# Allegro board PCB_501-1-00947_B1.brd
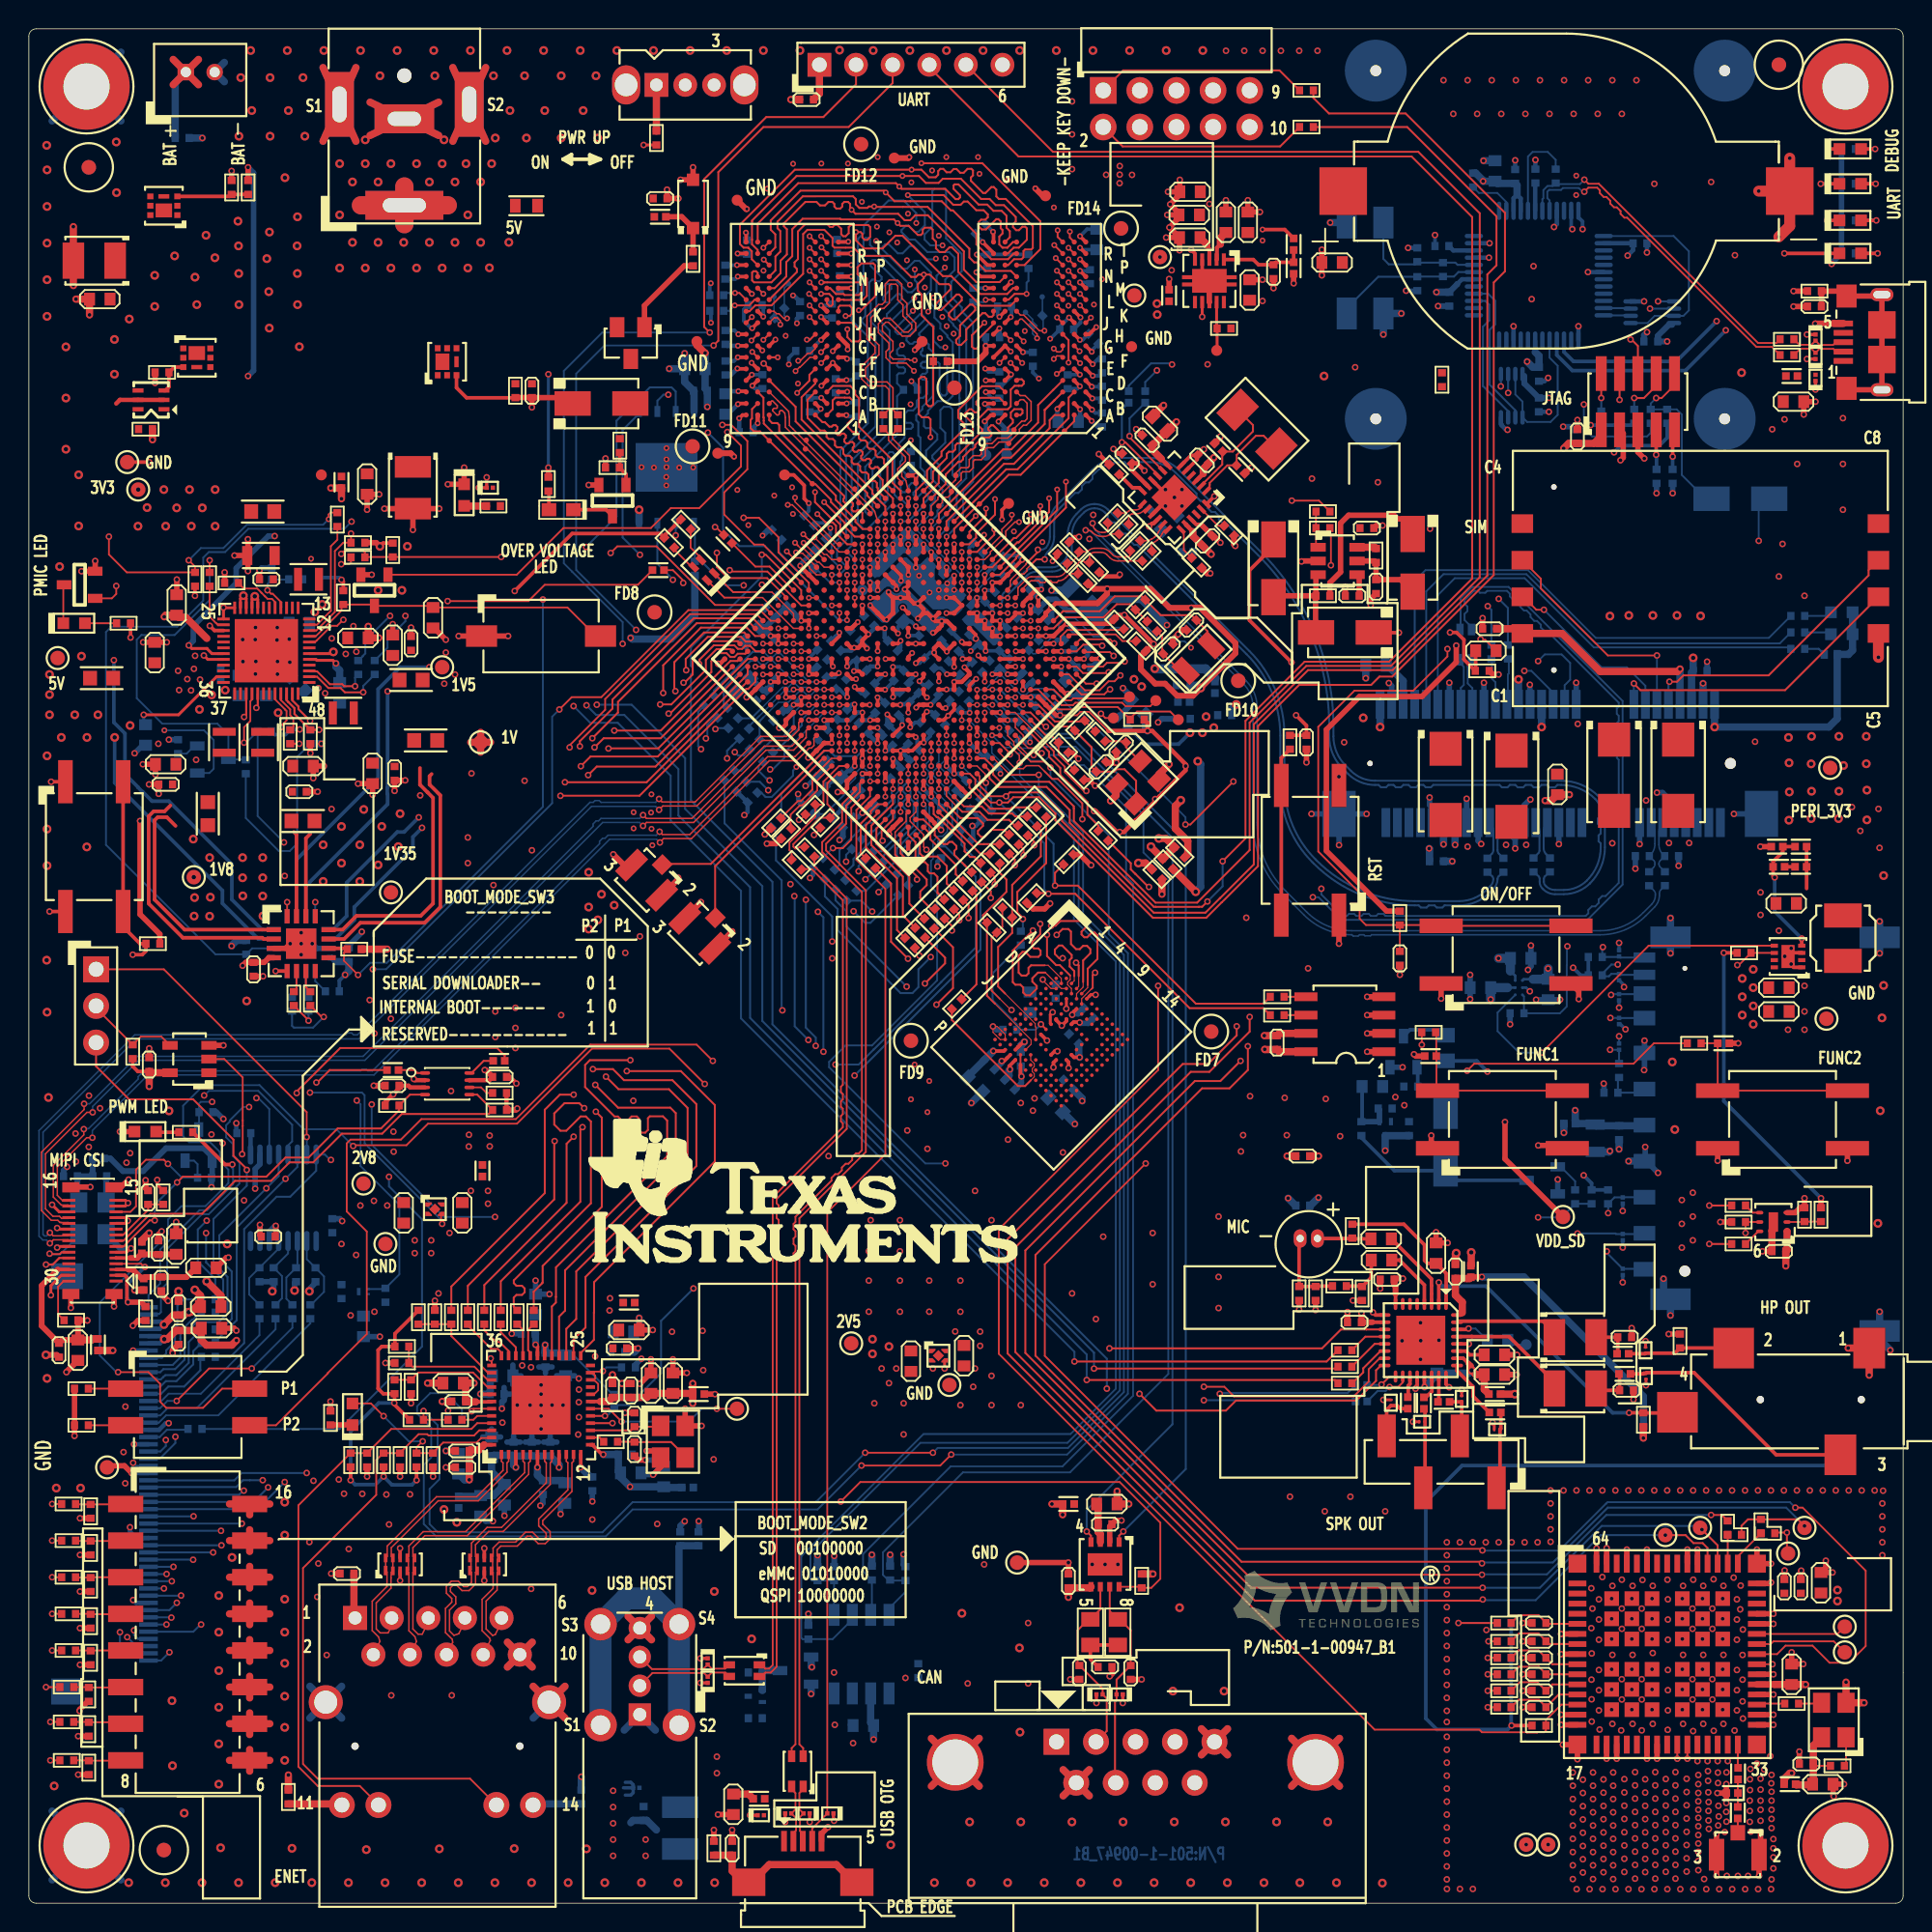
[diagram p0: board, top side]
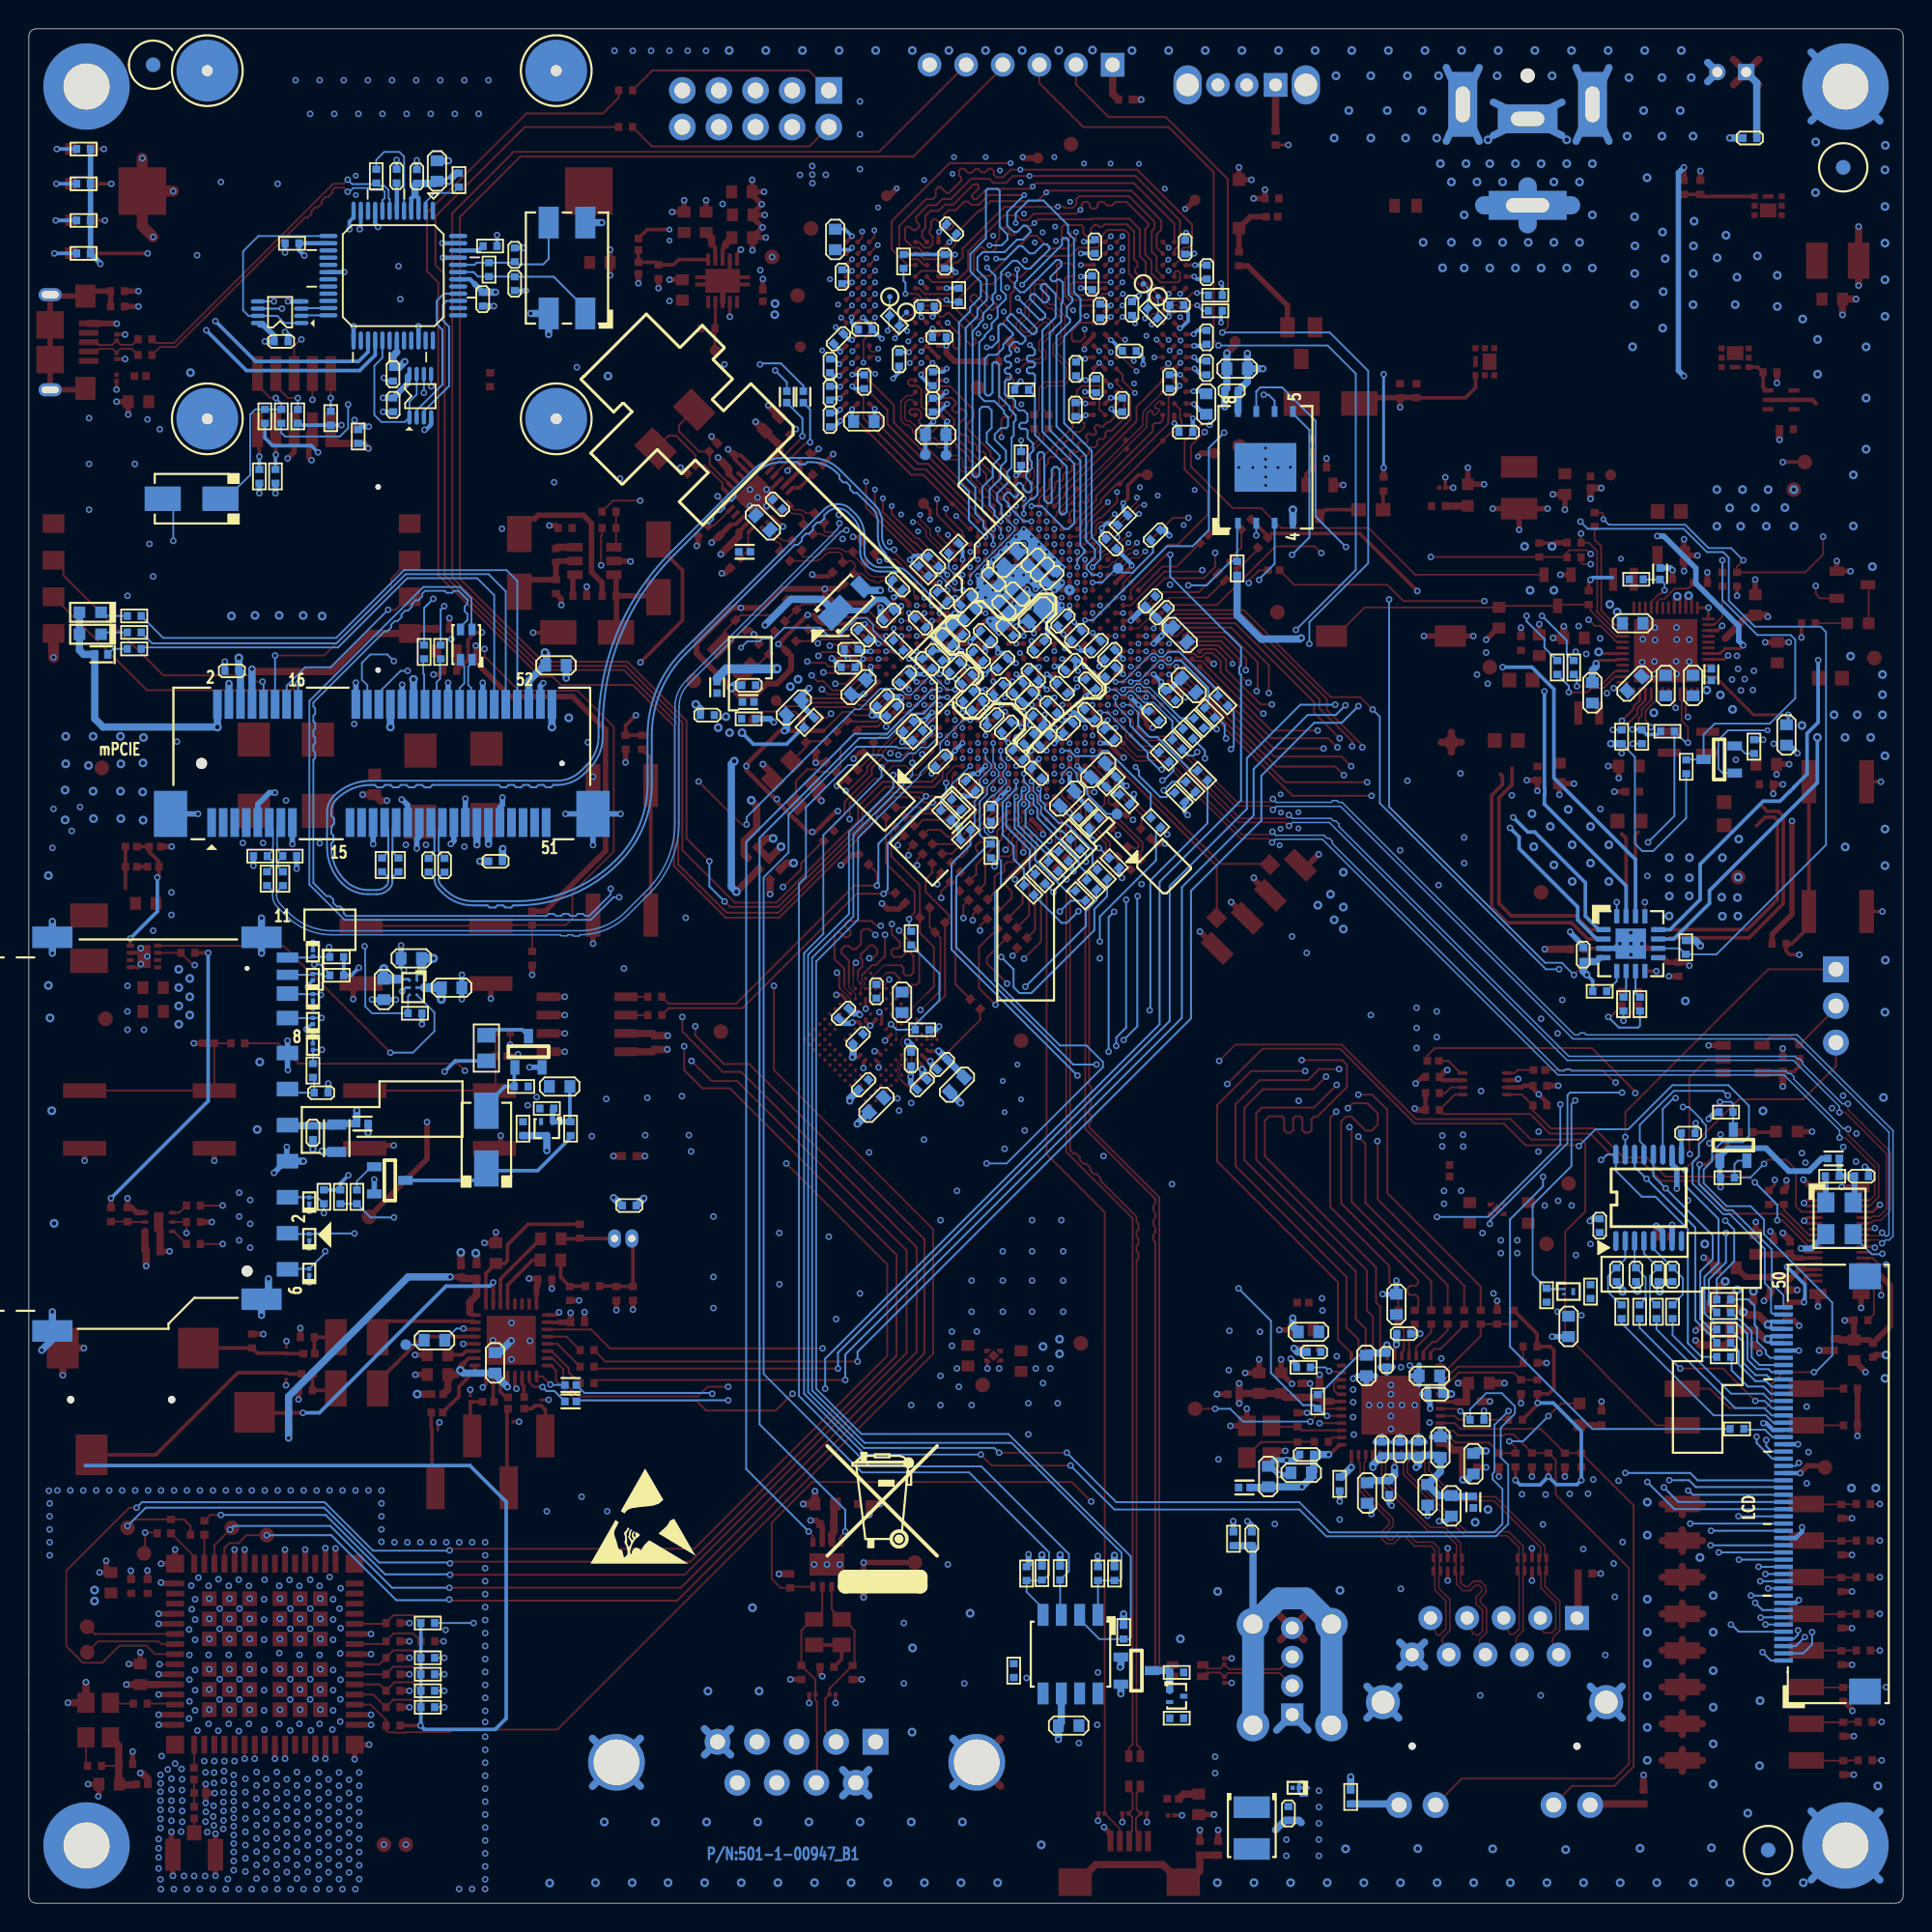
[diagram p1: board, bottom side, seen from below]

Outline 130 x 130 mm; copper layers: TOP, L2_GND_1, L3_INT_1, L4_PWR_1, L5_PWR_2, L6_INT_2, L7_GND_2, BOTTOM. Coordinates in mm from the lower left corner of the outline.
Outline path: 0,129.49 0,0.51 arc(0.15,0.15) 0.51,0 129.49,0 arc(129.85,0.15) 130,0.51 130,129.49 arc(129.85,129.85) 129.49,130 0.51,130 arc(0.15,129.85) 0,129.49

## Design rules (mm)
constraint set DEFAULT: min track width 0.127
net group D_USB_1: nets D_USB_DN D_USB_DP
net group DIFFPAIR63: nets MIPI_CSI_D0_N MIPI_CSI_D0_P
net group DIFFPAIR64: nets MIPI_CSI_D1_N MIPI_CSI_D1_P
net group DIFFPAIR65: nets MIPI_CSI_CLK_N MIPI_CSI_CLK_P
net group DIFFPAIR72: nets DDR_SDCLK0_N DDR_SDCLK0_P
net group DIFFPAIR75: nets CLKGEN_Q0_N CLKGEN_Q0_P
net group ETH-50OHMS: nets ENET_MDC ENET_MDIO
net group GPIO_SD3_DATA0: nets GPIO_SD3_DATA0 SD3_DATA0
net group GPIO_SD3_DATA1: nets GPIO_SD3_DATA1 SD3_DATA1
net group GPIO_SD3_DATA2: nets GPIO_SD3_DATA2 SD3_DATA2
net group GPIO_SD3_DATA3: nets GPIO_SD3_DATA3 SD3_DATA3
net group GPIO_SD3_DATA4: nets GPIO_SD3_DATA4 SD3_DATA4
net group GPIO_SD3_DATA5: nets GPIO_SD3_DATA5 SD3_DATA5
net group GPIO_SD3_DATA6: nets GPIO_SD3_DATA6 SD3_DATA6
net group GPIO_SD3_DATA7: nets GPIO_SD3_DATA7 SD3_DATA7
net group I2C_PCIE: nets PCIE_SMB_CLK PCIE_SMB_DATA
net group PCIE: nets PCIE_TX_N PCIE_TX_P
net group PCIE_CN: nets PCIE_CTXM PCIE_CTXP
net group PCIE_CREFCLK: nets PCIE_REFCLKOUT_N PCIE_REFCLKOUT_P
net group PCIE_REF-CLK_1: nets CLKGEN_Q1_N CLKGEN_Q1_P
net group PCIE_REFCLK: nets PCIE_REFCLK_N PCIE_REFCLK_P
net group PCIE_REFCLK-OUT: nets PCIE_REFCLKOUT_N0 PCIE_REFCLKOUT_P0
net group PCIE_RX_N: nets PCIE_RX_N PCIE_RXN_R
net group PCIE_RX_P: nets PCIE_RX_P PCIE_RXP_R
net group PCIE_USB_D: nets PCIE_USB_DM PCIE_USB_DP
net group RGMII1_RX_CTL: nets RGMII1_RX_CTL RX_CTRL
net group RGMII1_RXC: nets RGMII1_RXC RX_CLK
net group RGMII1_RXD0: nets RGMII1_RXD0 RX_D0
net group RGMII1_RXD1: nets RGMII1_RXD1 RX_D1
net group RGMII1_RXD2: nets RGMII1_RXD2 RX_D2
net group RGMII1_RXD3: nets RGMII1_RXD3 RX_D3
net group RGMII1_TX_CTL: nets RGMII1_TX_CTL RGMII_TCTRL
net group RGMII1_TXC: nets RGMII1_TXC RGMII_TXC
net group RGMII1_TXD0: nets RGMII1_TXD0 RGMII_TD0
net group RGMII1_TXD1: nets RGMII1_TXD1 RGMII_TD1
net group RGMII1_TXD2: nets RGMII1_TXD2 RGMII_TD2
net group RGMII1_TXD3: nets RGMII1_TXD3 RGMII_TD3
net group SD1_CMD: nets SD1_CMD SOC_SD1_CMD
net group SD2_CLK: nets SD2_CLK SOC_SD2_CLK
net group SPKOUTR: nets SPKRN SPKRP
net group USB_D2: nets USB_DN USB_DP
net group USB_HOST: nets USB_HOST_N USB_HOST_P
net group USB_HOST_D: nets USB_PCIE_DN USB_PCIE_DP
net group USB_OTG: nets USB_OTG_N USB_OTG_P
net group USB_OTG1_D: nets USB_OTG1_DN USB_OTG1_DP
net group USB_OTG2_DN: nets SOC_OTG2_DN USB_OTG2_DN
net group USB_OTG2_DP: nets SOC_OTG2_DP USB_OTG2_DP
net group GPIO_SD3_CMD: nets GPIO_SD3_CMD
net group LCD1_CLK: nets LCD1_CLK
net group PCIE_UIM: nets PCIE_UIM_CLK PCIE_UIM_DATA PCIE_UIM_PWR PCIE_UIM_RST PCIE_UIM_VPP
net group SD1_CLK: nets SOC_SD1_CLK
net group SD1_DATA0: nets SOC_SD1_DATA0
net group SD1_DATA1: nets SOC_SD1_DATA1
net group SD1_DATA2: nets SOC_SD1_DATA2
net group SD1_DATA3: nets SOC_SD1_DATA3
net group SD2_CMD: nets SOC_SD2_CMD
net group SD2_DATA0: nets SOC_SD2_DATA0
net group SD2_DATA1: nets SOC_SD2_DATA1
net group SD2_DATA2: nets SOC_SD2_DATA2
net group SD2_DATA3: nets SOC_SD2_DATA3
net group SD3_CLK_R: nets GPIO_SD3_CLK SD3_CLK SD3_CLK_R
net group SD3_RESET_B: nets GPIO_SD3_RESET_B
net group SD3_STROBE: nets GPIO_SD3_STROBE SD3_STROBE SD3_STROBE_R
net group SPKOUTL: nets SPKLP SPKOUTLN SPKOUTLP
net group WL_SD: nets WL_SDIO_CLK WL_SDIO_CMD WL_SDIO_D0 WL_SDIO_D1 WL_SDIO_D2 WL_SDIO_D3
nets with their own width: min track width 0.127; nets GND

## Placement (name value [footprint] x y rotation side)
BH1  BU2032SM-JJ-GTR  [CON_BATTERY_2F_30P97_SM]  106.65 118.75 0 top
C1  100uF  [TCAP_CASEB]  26.64 98.17 270 top
C2  22uF  [C0603]  23.46 98.42 270 top
C3  1uF  [0402]  21.68 98.55 270 top
C40  22uF  [C0603]  23.84 78.36 270 top
C41  22uF  [C0603]  19.02 78.87 0 top
C42  22uF  [C0603]  9.49 78.99 180 top
C44  22uF  [C0603]  25.24 87.25 90 top
C45  22uF  [C0603]  10.25 90.04 90 top
C46  47uF  [0805_B_A1]  16.1 93.47 180 top
C47  0.1uF  [C0402]  16.48 91.82 180 top
C48  22uF  [C0603]  22.83 87.76 0 top
C49  22uF  [C0603]  8.73 86.74 90 top
C50  4.7uF  [C0603]  18.64 84.58 135 bottom
C51  4.7uF  [C0603]  14.57 84.45 90 bottom
C52  4.7uF  [C0603]  18.76 88.77 180 bottom
C53  4.7uF  [C0603]  16.48 84.45 90 bottom
C63  0.22uF  [C0402]  52.21 90.32 135 bottom
C64  0.22uF  [C0402]  51.41 89.5 135 bottom
C65  22uF  [C0603]  49.55 84.48 225 bottom
C66  0.22uF  [C0402]  65.57 88.33 225 bottom
C67  2.2uF  [C0402]  60.33 85.15 45 bottom
C68  0.22uF  [C0402]  63.27 75.5 270 bottom
C69  0.22uF  [C0402]  64.68 77.5 225 bottom
C70  0.22uF  [C0402]  55.04 81.06 225 bottom
C71  0.22uF  [C0402]  51.96 82.35 225 bottom
C72  0.22uF  [C0402]  50.81 83.76 225 bottom
C73  22uF  [C0603]  50.17 87.96 225 bottom
C74  0.22uF  [C0402]  66.66 90.61 45 bottom
C75  0.22uF  [C0402]  65.01 90.35 135 bottom
C76  2.2uF  [C0402]  68.16 88.8 45 bottom
C77  2.2uF  [C0402]  57.75 85.85 315 bottom
C78  0.22uF  [C0402]  66.3 87.62 225 bottom
C79  0.22uF  [C0402]  68.99 81.61 315 bottom
C80  0.22uF  [C0402]  62.36 89.88 45 bottom
C81  0.22uF  [C0402]  62.08 88.26 225 bottom
C82  0.22uF  [C0402]  66.77 79.19 315 bottom
C83  0.22uF  [C0402]  61.41 90.81 45 bottom
C84  0.22uF  [C0402]  54.98 85.38 315 bottom
C85  22uF  [C0603]  60.15 89.39 315 bottom
C86  0.22uF  [C0402]  70.82 83.37 315 bottom
C87  2.2uF  [C0402]  70.14 82.68 315 bottom
C88  0.22uF  [C0402]  59.05 82.9 225 bottom
C89  2.2uF  [C0402]  64.14 86.48 225 bottom
C90  0.22uF  [C0402]  80.07 84.47 0 bottom
C91  2.2uF  [C0402]  67.69 85.98 45 bottom
C92  0.22uF  [C0402]  55.03 86.6 135 bottom
C93  0.22uF  [C0402]  66.97 86.52 45 bottom
C94  0.22uF  [C0402]  70.37 89.32 315 bottom
C95  2.2uF  [C0402]  69.74 91.44 45 bottom
C96  4.7uF  [C0603]  76.94 82.93 315 bottom
C97  2.2uF  [C0402]  72.14 87.97 45 bottom
C98  0.22uF  [C0402]  64.91 84.88 315 bottom
C99  0.22uF  [C0402]  65.78 85.72 315 bottom
C100  2.2uF  [C0402]  63.65 87.91 225 bottom
C101  0.22uF  [C0402]  56.41 82.45 45 bottom
C102  18pF  [C0402]  80.64 88.65 225 top
C103  18pF  [C0402]  79.01 87 45 top
C104  0.22uF  [C0402]  60.12 78.37 225 bottom
C105  18pF  [C0402]  74.38 78.82 45 top
C106  18pF  [C0402]  75.76 80.17 225 top
C107  0.22uF  [C0402]  69.27 84.99 315 bottom
C108  0.22uF  [C0402]  61.42 79.63 225 bottom
C109  2.2uF  [C0402]  55.98 87.22 135 bottom
C110  0.22uF  [C0402]  63.2 82.07 315 bottom
C111  2.2uF  [C0402]  62.18 81.56 315 bottom
C112  0.47uF  [C0402]  58.28 88.94 135 bottom
C113  0.47uF  [C0402]  56.35 84.56 225 bottom
C114  0.47uF  [C0402]  57.32 87.92 135 bottom
C115  2.2uF  [C0402]  58.33 84.25 45 bottom
C116  2.2uF  [C0402]  59.92 87.21 315 bottom
C117  0.22uF  [C0402]  57.9 81.51 135 bottom
C118  0.22uF  [C0402]  64.21 83.08 315 bottom
C119  0.22uF  [C0402]  60 82.05 45 bottom
C120  2.2uF  [C0402]  60.64 80.75 315 bottom
C121  10uF  [C0603]  57.99 76.62 315 bottom
C122  0.22uF  [C0402]  59.55 80.63 135 bottom
C123  10uF  [C0603]  55.83 78.58 135 bottom
C124  0.22uF  [C0402]  62.74 84.17 135 bottom
C125  0.22uF  [C0402]  60.75 83.65 135 bottom
C126  2.2uF  [C0402]  61.37 84.28 135 bottom
C127  0.22uF  [C0402]  64.85 83.7 315 bottom
C128  2.2uF  [C0402]  62.45 86 135 bottom
C129  0.22uF  [C0402]  82.94 82.4 0 bottom
C130  0.22uF  [C0402]  72.96 86.97 0 bottom
C131  2.2uF  [C0402]  73.17 85.72 0 bottom
C140  0.22uF  [C0402]  54.93 94.28 225 bottom
C141  0.1uF  [C0402]  67.26 93.05 45 bottom
C142  0.22uF  [C0402]  50.38 110.84 180 bottom
C143  0.22uF  [C0402]  50.88 105.53 270 bottom
C144  0.22uF  [C0402]  57.41 103.59 90 bottom
C145  0.22uF  [C0402]  66 116.12 45 bottom
C146  0.22uF  [C0402]  53.49 110.6 270 bottom
C147  0.22uF  [C0402]  56.06 114.91 90 bottom
C148  22uF  [C0603]  61.92 93.17 315 bottom
C149  0.22uF  [C0402]  56.25 112.39 270 bottom
C150  0.22uF  [C0402]  55.7 110.43 270 bottom
C151  0.22uF  [C0402]  55.96 105.24 90 bottom
C152  0.22uF  [C0402]  48.32 106.48 90 bottom
C153  0.22uF  [C0402]  67.31 103.9 270 bottom
C154  0.22uF  [C0402]  63.09 91.82 225 bottom
C155  0.22uF  [C0402]  54.16 103.91 270 bottom
C156  22uF  [C0603]  67.1 101.84 180 bottom
C157  0.22uF  [C0402]  48.3 113.13 90 bottom
C158  0.22uF  [C0402]  67.31 105.72 270 bottom
C159  0.22uF  [C0402]  74.43 104.73 90 bottom
C160  0.22uF  [C0402]  53.67 107.66 180 bottom
C161  0.22uF  [C0402]  73.6 112.81 270 bottom
C162  0.22uF  [C0402]  74.43 106.62 270 bottom
C163  0.22uF  [C0402]  72.05 105.52 90 bottom
C164  22uF  [C0603]  74.07 115.39 90 bottom
C165  0.22uF  [C0402]  71.98 109.15 180 bottom
C166  0.22uF  [C0402]  73.85 108.5 315 bottom
C167  0.22uF  [C0402]  67.68 110.74 0 bottom
C168  0.22uF  [C0402]  69.64 107.08 270 bottom
C169  0.22uF  [C0402]  49.8 114.86 90 bottom
C170  0.22uF  [C0402]  66.85 108.61 180 bottom
C171  0.22uF  [C0402]  60.34 93.14 315 bottom
C172  22uF  [C0603]  48.34 103.98 270 bottom
C173  0.22uF  [C0402]  59.05 91.92 315 bottom
C174  0.22uF  [C0402]  66.48 113.87 90 bottom
C175  0.22uF  [C0402]  48.32 108.6 270 bottom
C176  0.22uF  [C0402]  57.37 106.41 270 bottom
C177  0.22uF  [C0402]  49.75 102.03 180 bottom
C178  0.22uF  [C0402]  74.44 102.87 90 bottom
C179  0.22uF  [C0402]  59.71 92.51 315 bottom
C180  22uF  [C0603]  72.09 102.77 180 bottom
C181  0.1uF  [C0402]  72.48 59.94 315 bottom
C182  0.1uF  [C0402]  72.1 56.77 315 bottom
C183  4.7uF  [C0603]  71.21 55.37 315 bottom
C184  0.1uF  [C0402]  66.64 58.17 315 bottom
C185  0.1uF  [C0402]  68.04 56.77 315 bottom
C186  0.1uF  [C0402]  68.8 58.55 270 bottom
C187  0.1uF  [C0402]  73.5 61.72 315 bottom
C188  4.7uF  [C0603]  65.63 56.77 315 bottom
C189  4.7uF  [C0603]  46.19 106.43 0 bottom
C190  0.22uF  [C0402]  46.58 104.9 0 bottom
C194  1uF  [C0603]  93.18 56.64 180 bottom
C195  47uF  [0805_B_A1]  108.64 53.05 270 bottom
C196  0.1uF  [C0402]  110.3 53.43 270 bottom
C197  18pF  [C0402]  109.73 56.21 180 bottom
C199  100uF  [TCAP_CASEC]  114.39 78.23 270 top
C200  4.7uF  [C0603]  106.01 77.6 270 top
C201  0.1uF  [C0402]  97.63 72.26 180 bottom
C202  100uF  [TCAP_CASEC]  102.84 77.47 270 top
C203  100uF  [TCAP_CASEC]  98.26 77.6 270 top
C204  100uF  [TCAP_CASEC]  109.95 78.23 270 top
C207  0.1uF  [C0402]  102.27 71.99 90 bottom
C208  0.1uF  [C0402]  101.17 71.99 90 bottom
C216  1uF  [C0603]  122.27 15.88 90 top
C217  0.1uF  [C0402]  122.9 21.97 90 top
C218  10uF  [C0603]  124.3 22.22 90 top
C219  18pF  [C0402]  104.74 13.59 180 top
C220  18pF  [C0402]  104.74 14.73 180 top
C221  18pF  [C0402]  104.74 15.88 180 top
C222  18pF  [C0402]  104.74 17.02 180 top
C223  18pF  [C0402]  104.74 19.43 180 top
C224  18pF  [C0402]  104.74 18.16 180 top
C226  10uF  [C0603]  101.69 120.14 90 bottom
C227  0.1uF  [C0402]  98.52 111.25 270 bottom
C228  0.1uF  [C0402]  104.74 106.05 270 bottom
C239  4.7uF  [C0603]  122.39 104.14 0 top
C240  0.1uF  [C0402]  104.49 119.79 90 bottom
C241  0.22uF  [C0402]  112.5 108.32 180 bottom
C242  0.1uF  [C0402]  123.85 110.74 180 top
C243  18pF  [C0402]  96.3 112.32 90 bottom
C244  18pF  [C0402]  96.3 114.33 270 bottom
C245  0.22uF  [C0402]  104.73 103.92 270 bottom
C249  1uF  [C0603]  37.23 37.29 270 bottom
C250  1uF  [C0603]  43.15 36.07 90 top
C251  0.01uF  [C0402]  40.99 38.48 0 top
C252  0.1uF  [C0402]  48.78 3.81 90 top
C260  1uF  [C0603]  93.82 44.6 180 top
C261  22uF  [C0603]  12.62 41.38 0 top
C262  0.1uF  [C0402]  10.38 41.27 90 top
C263  22uF  [C0603]  12.67 39.88 0 top
C264  0.1uF  [C0402]  10.38 39.23 270 top
C265  0.22uF  [C0402]  21.05 46.99 90 bottom
C266  0.1uF  [C0402]  14.91 53.41 0 bottom
C267  0.1uF  [C0402]  91.94 40.29 180 top
C268  0.1uF  [C0402]  94.21 43.26 180 top
C269  4.7uF  [C0603]  97.66 37.47 90 bottom
C270  4.7uF  [C0603]  101.65 36.66 0 top
C271  0.1uF  [C0402]  98.94 43.81 90 top
C272  4.7uF  [C0603]  97.6 45.09 90 top
C273  4.7uF  [C0603]  101.65 38.03 0 top
C274  100uF  [TCAP_CASEB]  107.26 39.25 0 top
C275  100uF  [TCAP_CASEB]  107.26 35.7 0 top
C276  1uF  [C0603]  101.87 39.04 0 bottom
C279  0.1uF  [C0402]  74.64 26.29 0 top
C280  10uF  [C0603]  44.04 29.59 90 bottom
C281  56pF  [C0402]  72.86 16 270 top
C282  56pF  [C0402]  76.42 16 270 top
C283  0.1uF  [C0402]  30.07 30.23 180 top
C284  1uF  [C0603]  41.75 29.84 0 bottom
C285  1uF  [C0603]  29.81 30.48 90 bottom
C286  10uF  [C0603]  31.34 27.56 270 bottom
C287  0.01uF  [C0402]  36.16 31.5 90 bottom
C288  0.1uF  [C0402]  34.89 31.5 90 bottom
C289  0.1uF  [C0402]  33.62 31.5 90 bottom
C290  1uF  [C0603]  32.1 31.62 90 bottom
C291  1uF  [C0603]  32.99 28.32 270 bottom
C292  10uF  [C0603]  44.67 36.07 90 top
C293  0.01uF  [C0402]  40.48 35.56 90 top
C294  0.1uF  [C0402]  41.75 35.56 90 top
C295  0.1uF  [C0402]  32.48 35.31 0 bottom
C296  0.1uF  [C0402]  35.83 37.67 270 bottom
C297  1uF  [C0603]  32.86 36.58 0 bottom
C298  4.7uF  [C0603]  48.86 6.86 270 top
C299  100uF  [TCAP_CASEB]  45.18 5.21 270 bottom
C300  0.1uF  [C0402]  42.64 6.22 90 bottom
C301  0.1uF  [C0402]  45.18 25.27 90 bottom
C302  0.1uF  [C0402]  35.65 28.83 270 bottom
C303  0.1uF  [C0402]  34.64 39.5 180 bottom
C304  18pF  [C0402]  42 31.5 270 top
C305  18pF  [C0402]  42 33.53 90 top
C306  0.1uF  [C0402]  40.86 38.23 0 bottom
C307  0.1uF  [C0402]  29.81 34.8 180 top
C308  1uF  [C0603]  35.15 41.53 90 bottom
C309  1uF  [C0603]  41.24 39.62 0 bottom
C310  1uF  [C0603]  29.43 36.07 180 top
C311  1uF  [C0603]  37.18 28.45 270 bottom
C318  1uF  [C0603]  93.79 46.08 180 top
C354  4.7uF  [C0603]  10.22 45.71 90 top
C357  0.22uF  [C0402]  64.73 89.39 135 bottom
C361  0.1uF  [C0402]  103.09 119.76 90 bottom
C362  22uF  [C0603]  72.46 84.34 315 bottom
C366  18pF  [C0402]  51.86 94.89 135 bottom
C367  0.1uF  [C0402]  95.09 65.53 270 top
C368  0.1uF  [C0402]  88.61 80.52 270 top
C369  1000pF  [C0402]  110.69 39.25 0 top
C370  1000pF  [C0402]  110.81 35.57 0 top
C382  1uF  [C0603]  101.06 86.87 180 top
C391  0.1uF  [C0402]  121.38 45.21 180 top
C392  0.1uF  [C0402]  8.35 58.17 90 top
C393  0.033uF  [C0402]  91.79 90.68 180 top
C394  0.01uF  [C0402]  34.89 104.9 270 top
C395  0.1uF  [C0402]  43.78 118.24 0 top
C401  2.2uF  [C0402]  93.44 91.31 270 top
C402  27pF  [0402]  84.04 99.44 315 top
C403  27pF  [0402]  82.52 100.97 135 top
C404  10uF  [C0603]  79.09 95.76 45 bottom
C405  0.1uF  [C0402]  78.07 97.03 45 bottom
C406  1uF  [C0603]  78.45 102.62 135 top
C407  0.01uF  [C0402]  76.17 100.2 135 top
C408  0.22uF  [C0402]  86.58 59.69 90 top
C409  0.01uF  [C0402]  81.75 94.49 45 top
C410  0.01uF  [C0402]  81.37 100.08 135 top
C420  18pF  [C0402]  19.88 43.59 90 bottom
C421  18pF  [C0402]  18.53 43.59 90 bottom
C422  18pF  [C0402]  16.98 43.59 90 bottom
C423  18pF  [C0402]  15.99 43.59 90 bottom
C438  100uF  [TCAP_CASEB]  4.54 113.92 180 top
C439  22uF  [C0603]  4.92 111.25 180 top
C444  0.1uF  [C0402]  9.19 42.95 270 top
C445  4.7uF  [C0603]  12.29 44.07 0 top
C446  0.1uF  [C0402]  2.09 38.35 270 top
C447  4.7uF  [C0603]  3.4 38.35 270 top
C448  0.1uF  [C0402]  2.89 50.42 180 bottom
C456  0.1uF  [C0402]  8.27 48.95 90 top
C460  0.1uF  [C0402]  32.65 57.31 0 top
C461  0.1uF  [C0402]  25.2 56.7 180 top
C500  10uF  [C0603]  41.62 39.75 0 top
C501  0.1uF  [C0402]  8.98 45.47 90 top
C503  0.1uF  [C0402]  115.92 85.47 0 bottom
C504  4.7uF  [C0603]  93.44 85.85 180 bottom
C505  0.1uF  [C0402]  72.1 22.35 90 top
C506  0.01uF  [C0402]  74.64 16.38 0 top
C507  0.01uF  [C0402]  30.07 31.37 180 top
C508  0.1uF  [C0402]  41.37 31.11 0 bottom
C509  0.01uF  [C0402]  77.56 101.47 135 top
C510  0.1uF  [C0402]  71.21 63.25 270 bottom
C511  1uF  [C0603]  69.44 62.48 270 bottom
C512  10uF  [C0603]  121.38 63.5 0 top
C513  10uF  [C0603]  121.38 61.85 0 top
C518  22uF  [C0603]  121.89 69.34 180 top
C519  10uF  [C0603]  26 47.88 270 top
C520  10uF  [C0603]  30.07 47.88 270 top
C523  10uF  [C0603]  61.18 37.59 270 top
C524  10uF  [C0603]  64.86 37.97 270 top
C525  22uF  [C0603]  57.88 12.32 0 bottom
C527  0.01uF  [C0402]  123.28 9.65 180 top
C528  10uF  [C0603]  124.43 8.25 0 top
C529  10pF  [0402]  118.55 8.98 90 top
C530  8pF  [0402]  118.53 6.28 90 top
C531  3.3pF  [0402]  122.9 73.28 180 top
C533  10uF  [C0603]  83.02 116.59 90 top
C534  1000pF  [C0402]  86.33 113.16 270 top
C535  4.7uF  [0402]  79.09 111.51 90 top
C536  4.7uF  [C0603]  84.68 111.89 90 top
C537  10uF  [C0603]  84.55 116.59 90 top
C538  10uF  [C0603]  80.48 117.09 180 top
C539  10uF  [C0603]  80.52 115.52 180 top
C540  10uF  [C0603]  80.54 118.7 180 top
C542  1uF  [C0603]  8.09 81.03 270 bottom
C543  0.1uF  [C0402]  121.76 21.97 90 top
C544  4.7uF  [C0603]  23.21 40.01 270 bottom
C546  4.7uF  [C0603]  21.56 83.95 270 bottom
C550  0.1uF  [C0402]  25.37 78.36 270 top
C551  0.1uF  [C0402]  18.76 77.09 0 top
C552  0.1uF  [C0402]  9.49 77.6 180 top
C553  0.1uF  [C0402]  26.51 87.38 90 top
C556  1uF  [C0603]  28.03 89.15 90 top
C557  4.7uF  [C0603]  90.39 113.79 180 top
C558  0.1uF  [C0402]  16.6 46.23 0 top
C559  10uF  [C0603]  105.38 63.37 270 bottom
C560  10uF  [C0603]  103.47 65.53 0 bottom
C561  10uF  [C0603]  100.68 63.5 180 bottom
C566  0.1uF  [C0402]  15.59 64.77 270 top
C567  0.1uF  [C0402]  22.19 65.79 90 bottom
C568  1uF  [0402]  13.3 85.22 90 bottom
C569  0.1uF  [C0402]  10.63 122.43 0 bottom
C570  10uF  [C0603]  74.77 27.69 0 top
C571  0.1uF  [C0402]  101.31 88.39 180 top
C572  0.1uF  [C0402]  107.41 101.73 90 top
C573  0.1uF  [C0402]  92.8 95.38 0 top
C574  0.1uF  [C0402]  88.36 51.82 180 top
C575  0.1uF  [C0402]  88.36 48.39 180 bottom
C576  0.22uF  [C0402]  22.06 22.86 180 top
C577  0.1uF  [C0402]  53.94 125.09 180 top
C578  1uF  [0402]  97.22 58.75 180 top
C579  1uF  [0402]  117.54 59.64 0 top
D1  G  [LED2_1P5_1P6X0P8_A_A1]  30.19 97.66 270 top
D2  R  [LED-0603]  36.92 96.65 180 top
D4  B140-13-F  [DIO_SMA]  98.26 52.96 90 bottom
D5  O  [LED2_0P9_1X0P6]  124.98 86.61 180 bottom
D6  G  [LED2_1P5_1P6X0P8_A_A1]  125.74 88.01 0 bottom
D7  R  [LED2_1P5_1P6X0P8_A_A1]  125.74 89.53 0 bottom
D8  R  [LED2_1P5_1P6X0P8_A_A1]  126.33 121.67 0 top
D9  G  [LED2_1P5_1P6X0P8_A_A1]  126.33 119.25 0 top
D10  R  [LED2_1P5_1P6X0P8_A_A1]  126.33 116.71 0 top
D11  G  [LED2_1P5_1P6X0P8_A_A1]  126.33 114.43 0 top
D14  G  [LED2_1P5_1P6X0P8_A_A1]  22.45 33.91 90 top
D16  B140-13-F  [DIO_SMA]  95.98 92.96 270 top
D17  BZT52C5V1  [DIO-SOD123_D_A1]  46.07 117.86 90 top
D20  B140-13-F  [DIO_SMA]  39.72 104.01 0 top
D21  B140-13-F  [DIO_SMA]  86.33 92.58 270 top
D22  B140-13-F  [DIO_SMA]  91.28 88.14 180 top
D23  PESD5V0V1BSF  [DIO-SOD962-2_A1]  112.13 38.35 270 top
D24  PESD5V0V1BSF  [DIO-SOD962-2_A1]  112.16 36.56 90 top
D26  B140-13-F  [DIO_SMA]  118.71 97.41 0 bottom
D27  PESD5V0V1BSF  [DIO-SOD962-2_A1]  101.84 32.86 0 top
D28  PESD5V0V1BSF  [DIO-SOD962-2_A1]  99.38 34.98 270 top
D29  PESD5V0V1BSF  [DIO-SOD962-2_A1]  96.63 33.39 0 top
D30  PESD5V0V1BSF  [DIO-SOD962-2_A1]  94.47 34.71 270 top
D33  G  [LED2_1P5_1P6X0P8_A_A1]  3.14 88.77 0 top
D34  DFLS130L-7  [DIO_POWERDI-123]  73.37 90.17 135 bottom
D35  R  [LED2_1P5_1P6X0P8_A_A1]  8.08 53.51 0 top
DA1  HSMF-C165  [LED4_0P7_1P6X0P8]  46.83 92.46 315 top
F1  5A, 32V  [FUSE_0603_0P64]  34.51 117.73 0 top
FB2  120E  [0402]  80.1 83.31 180 bottom
FB3  120E  [0402]  82.26 84.33 90 bottom
FB4  120E  [0402]  80.36 93.73 180 bottom
FB10  120E  [0402]  122.27 105.92 180 top
FB11  120E  [0402]  110.56 38.11 0 top
FB12  120E  [0402]  110.69 36.71 0 top
FB13  120E  [0402]  96.76 34.68 270 top
FB14  120E  [0402]  101.69 34.04 0 top
FB16  120E  [0402]  95.64 34.7 270 top
FB17  120E  [0402]  98.14 34.77 0 top
FB18  120E  [0402]  50.64 7.24 180 top
FB19  120E  [0402]  45.69 28.83 0 bottom
FB20  120E  [0402]  29.81 27.81 270 bottom
FB21  120E  [0402]  46.45 35.31 0 top
FB22  120E  [0402]  41.62 41.66 0 top
FB31  120E  [0402]  7.97 42.93 90 top
FB32  120E  [0402]  7.84 45.47 270 top
FB35  120E  [0402]  4.82 51.65 180 bottom
FB36  120E  [0402]  4.79 38.73 270 top
FB37  120E  [0402]  72.1 27.69 180 top
FB38  120E  [0402]  31.46 50.8 270 top
FB39  120E  [0402]  122.14 8.25 180 top
FB40  120E  [0402]  101.67 35.31 180 top
FB41  120E  [0402]  100.02 43.81 270 top
FB42  120E  [0402]  106.87 54.07 0 bottom
FD1  Global  [GFD40_120]  121.38 127.51 0 top
FD2  Global  [GFD40_120]  9.36 3.68 0 top
FD3  Global  [GFD40_120]  4.16 120.4 0 top
FD4  Global  [GFD40_120]  4.16 120.4 180 bottom
FD5  Global  [GFD40_120]  9.36 3.68 180 bottom
FD6  Global  [GFD40_120]  121.38 127.51 180 bottom
FD7  Local  [LFD40_80]  82.01 60.45 0 top
FD8  Local  [LFD40_80]  43.4 89.53 0 top
FD9  Local  [LFD40_80]  61.18 59.82 0 top
FD10  Local  [LFD40_80]  83.88 84.79 0 top
FD11  Local  [LFD40_80]  46.04 101.04 0 top
FD12  Local  [LFD40_80]  57.72 122 0 top
FD13  Local  [LFD40_80]  64.2 105.11 0 top
FD14  Local  [LFD40_80]  75.75 116.15 0 top
FL1  DLW21HN900SQ2L  [CM_CHK4_0P8_2X1P2]  53.31 9.14 90 top
FL2  DLW21HN900SQ2L  [CM_CHK4_0P8_2X1P2]  49.62 16.13 180 top
FL3  DLW21HN900SQ2L  [CM_CHK4_0P8_2X1P2]  99.66 87.29 90 bottom
H1  HDR_2X5  [CON_BERG_2X5M_2P54_TH_RA]  74.52 125.73 0 top
H2  HDR_2X5  [CON_B2B_2X5M_1P27_SM_ST]  111.6 104.14 0 top
H3  HDR_1X4  [CON_BERG_1X4M_2P54_SM_ST_A_A1]  97.99 30.61 180 top
H4  HDR_1X3  [CON_BERG_3M_2P54_TH_54101]  4.67 64.77 270 top
H5  HDR_1X6  [CON_BERG_6M_2P54_TH]  54.83 127.51 0 top
J1  CON_PWRJACK  [CON_PWR-JACK_2M_6_TH_RA_A_A1]  26.05 117.76 0 top
J2  CON_B2C_1X2  [CON_B2C_1X2M_2_TH_ST_A]  10.89 127 0 top
J3  CON_COAX  [CON_COAXIAL_3F_1P475_SM_ST]  42.85 70.95 135 top
J4  CON_COAX  [CON_COAXIAL_3F_1P475_SM_ST]  46.53 67.27 135 top
J7  CON_SIMCARD  [CON_SIM-CARD_8P_2P54_SM_RA]  115.94 91.88 90 top
J8  CON_MINI-PCIEXPRESS  [CON_PCI_2X26F_0P8_SM_RA_CUST_A1]  105.52 79.05 180 bottom
J10  CON_COAX  [CON_COAXIAL_3F_1P475_SM_ST]  118.53 3.36 180 top
J11  CON_USB Micro-B  [CON_USB_1X1-5F_0P65_SM_RA_D_A1]  125.85 108.27 90 top
J14  CON_FPC  [CON_FPC_50F_0P5_SM_RA]  4.5 29.08 90 bottom
J15  CON_AUDJACK  [CON_A-JACK3P5MM_4F_SM_RA]  124.05 34.8 180 top
J19  CON_DB9  [CON_DB_9M_2P74_5747840-4]  71.27 11.19 0 top
J20  CON_B2B_2X15  [FPC2X15_4P4_A]  4.41 45.95 90 top
J25  CON_USB MICRO-AB  [CON_USB_5F_0P65_SM_RA]  53.68 1.78 0 top
J26  CON_USBA  [CON_USB-A_1X1F_2_TH_RA_D_A1]  42.37 13.08 0 top
J27  CON_RJ45  [CON_RJ45_14F_2P54_TH_RA]  22.62 19.78 180 top
J28  CON_SD-CARD-11  [CON_SDCARD_11F_2P5_SM_RA_A_A1]  121.12 53.34 270 bottom
L3  1.5uH  [IND_0806_B_A1]  21.81 82.55 0 top
L4  1.5uH  [IND_0806_B_A1]  16.22 80.52 270 top
L5  1.5uH  [IND_0806_B_A1]  13.56 80.52 270 top
L6  1.5uH  [IND_0806_B_A1]  19.4 91.82 180 top
L7  1uH  [IND2_2P2_4X4]  125.82 66.93 90 top
L8  1.1nH  [IND_0402-POL]  118.14 7.64 180 top
M1  WL1831MOD  [MOD-WIFI-BT64_0P7_13P4X13P3]  113.63 17.27 270 top
MECH1  NT4R1600  [MECH-M2_RAD4_A1]  93.42 127.1 180 bottom
MECH2  NT4R1600  [MECH-M2_RAD4_A1]  117.62 127.1 180 bottom
MECH3  NT4R1600  [MECH-M2_RAD4_A1]  117.62 102.95 180 bottom
MECH4  NT4R1600  [MECH-M2_RAD4_A1]  93.42 102.95 180 bottom
MH1  126MILS  [MH236D126T_A1]  126 126 0 top
MH2  126MILS  [MH236D126T_A1]  4 126 0 top
MH3  126MILS  [MH236D126T_A1]  126 4 0 top
MH4  126MILS  [MH236D126T_A1]  4 4 0 top
MK1  TOM-1545P-R  [MIC2_1P2_4P1X4P1_TH]  89.37 46.1 180 top
NOREF  -  []  38.95 31.79 90 top
NOREF#2  -  []  79.58 83.04 90 top
NOREF#3  -  []  14.28 83.89 90 top
NOREF#4  -  []  91.9 34.52 0 top
NOREF#5  -  []  32.21 58.42 0 top
NOREF#6  -  []  59.66 14.55 90 top
NOREF#7  -  []  130.67 104.52 90 top
NOREF#8  -  []  15.42 95.32 90 top
NOREF#9  -  []  128.53 104.97 90 top
NOREF#10  -  []  96.93 33.24 90 top
NOREF#11  -  []  86.87 68.52 90 top
NOREF#12  -  []  77.23 97.04 0 top
NOREF#13  -  []  122.5 71.88 0 top
NOREF#14  -  []  20.79 66.87 90 top
NOREF#15  -  []  46.03 0.59 90 top
NOREF#16  -  []  84.61 98.71 90 top
NOREF#17  -  []  31.19 50.27 90 top
NOREF#18  -  []  97.96 63.79 90 top
NOREF#19  -  []  94.32 34.41 0 top
NOREF#20  -  []  120.73 73 0 top
NOREF#21  -  []  24.71 58.06 0 top
NOREF#22  -  []  15.42 96.52 0 top
NOREF#23  -  []  96.69 58.48 90 top
NOREF#24  -  []  55.85 14.55 0 top
NOREF#25  -  []  92.02 34.8 0 top
NOREF#26  -  []  79.83 93.45 90 top
NOREF#27  -  []  18.22 75.06 0 top
NOREF#28  -  []  122 46.24 90 top
NOREF#29  -  []  92.46 104.7 0 top
NOREF#30  -  []  125.85 107.62 90 top
NOREF#31  -  []  7.57 44.94 90 top
NOREF#32  -  []  101.27 35.31 0 top
NOREF#33  -  []  120 48.24 0 top
NOREF#34  -  []  79.83 93.45 0 top
NOREF#35  -  []  97.7 52.36 90 top
NOREF#36  -  []  94.07 53.23 90 top
NOREF#37  -  []  16.89 64.55 90 top
NOREF#38  -  []  39.65 12.35 90 top
NOREF#39  -  []  43.26 116.14 90 top
NOREF#40  -  []  91.97 69.57 90 top
NOREF#41  -  []  83.76 99.72 0 top
NOREF#42  -  []  45.29 28.83 0 top
NOREF#43  -  []  126.01 129 0 top
NOREF#44  -  []  110.16 36.44 0 top
NOREF#45  -  []  17.91 64.65 0 top
NOREF#46  -  []  38.71 0.59 0 top
NOREF#47  -  []  94.32 34.41 90 top
NOREF#48  -  []  101.24 74.47 0 top
NOREF#49  -  []  77.15 103.95 90 top
NOREF#50  -  []  101.29 34.04 0 top
NOREF#51  -  []  122.5 73.28 0 top
NOREF#52  -  []  20.89 64.55 90 top
NOREF#53  -  []  31.46 50.4 90 top
NOREF#54  -  []  50.79 13.75 90 top
NOREF#55  -  []  112.01 36.86 0 top
NOREF#56  -  []  7.69 43.45 0 top
NOREF#57  -  []  99.23 34.68 90 top
NOREF#58  -  []  46.84 116.51 90 top
NOREF#59  -  []  45.09 12.35 90 top
NOREF#60  -  []  79.09 111.11 90 top
NOREF#61  -  []  108.02 52.05 0 top
NOREF#62  -  []  83.48 99.62 0 top
NOREF#63  -  []  100.02 43.41 90 top
NOREF#64  -  []  102.84 75 90 top
NOREF#65  -  []  112.16 36.36 90 top
NOREF#66  -  []  95.64 34.3 90 top
NOREF#67  -  []  4.25 84.96 0 top
NOREF#68  -  []  28.66 47.63 90 top
NOREF#69  -  []  76.01 105 0 top
NOREF#70  -  []  -7.05 0 90 top
NOREF#71  -  []  21.05 116.76 0 top
NOREF#72  -  []  121.78 73 90 top
NOREF#73  -  []  106.47 54.07 0 top
NOREF#74  -  []  45.49 68.31 0 top
NOREF#75  -  []  117.13 56.36 0 top
NOREF#76  -  []  81.95 100.59 0 top
NOREF#77  -  []  112.13 38.15 90 top
NOREF#78  -  []  121.95 47.24 90 top
NOREF#79  -  []  41.81 71.99 0 top
NOREF#80  -  []  39.03 31.04 90 top
NOREF#81  -  []  0 129.49 0 top
NOREF#82  -  []  73.73 88.55 90 top
NOREF#83  -  []  95.37 34.17 0 top
NOREF#84  -  []  50.88 13.95 90 top
NOREF#85  -  []  32.1 37.29 0 top
NOREF#86  -  []  81.99 83.8 90 top
NOREF#87  -  []  32.03 38.04 0 top
NOREF#88  -  []  118.81 5.75 90 top
NOREF#89  -  []  97.74 34.77 0 top
NOREF#90  -  []  121.62 7.98 90 top
NOREF#91  -  []  79.58 83.04 0 top
NOREF#92  -  []  106.34 54.34 0 top
NOREF#93  -  []  120.85 73.28 0 top
NOREF#94  -  []  111.08 37.83 90 top
NOREF#95  -  []  116.66 128.85 0 top
NOREF#96  -  []  70.55 63.44 90 top
NOREF#97  -  []  96.43 33.39 0 top
NOREF#98  -  []  74.04 89.5 90 top
NOREF#99  -  []  110.29 36.71 0 top
NOREF#100  -  []  105.91 62.69 90 top
NOREF#101  -  []  77.15 105 0 top
NOREF#102  -  []  43.6 103.46 0 top
NOREF#103  -  []  79.96 93.73 0 top
NOREF#104  -  []  116.96 3.61 90 top
NOREF#105  -  []  50.11 7.51 0 top
NOREF#106  -  []  99.74 43.29 0 top
NOREF#107  -  []  15.1 94.1 0 top
NOREF#108  -  []  76.29 104.07 90 top
NOREF#109  -  []  47.92 94.79 90 top
NOREF#110  -  []  82.23 101.25 0 top
NOREF#111  -  []  16.99 66.87 90 top
NOREF#112  -  []  16.99 65.57 0 top
NOREF#113  -  []  4.79 38.33 90 top
NOREF#114  -  []  28.33 80.24 90 top
NOREF#115  -  []  99.74 43.29 90 top
NOREF#116  -  []  34.78 31.12 0 top
NOREF#117  -  []  42.37 13.08 90 top
NOREF#118  -  []  6.72 9.91 0 top
NOREF#119  -  []  81.99 84.85 0 top
NOREF#120  -  []  71.58 27.41 90 top
NOREF#121  -  []  118.26 6.8 0 top
NOREF#122  -  []  109.27 52.05 90 top
NOREF#123  -  []  4.25 83.76 90 top
NOREF#124  -  []  102.14 32.71 90 top
NOREF#125  -  []  87.45 115.59 0 top
NOREF#126  -  []  28.59 47.81 90 top
NOREF#127  -  []  -0.02 31.04 90 top
NOREF#128  -  []  42.85 72.79 0 top
NOREF#129  -  []  99.01 62.69 0 top
NOREF#130  -  []  39.65 19.35 0 top
NOREF#131  -  []  38.28 31.12 90 top
NOREF#132  -  []  89.42 93.09 90 top
NOREF#133  -  []  0 129.49 0 top
NOREF#134  -  []  71.58 27.96 0 top
NOREF#135  -  []  92.46 128.85 0 top
NOREF#136  -  []  101.14 35.58 0 top
NOREF#137  -  []  1.44 69.83 0 top
NOREF#138  -  []  125.62 106.97 90 top
NOREF#139  -  []  17.91 64.65 0 top
NOREF#140  -  []  6.72 9.91 90 top
NOREF#141  -  []  71.7 27.69 0 top
NOREF#142  -  []  1.44 69.83 90 top
NOREF#143  -  []  120.05 47.89 0 top
NOREF#144  -  []  118.55 8.58 90 top
NOREF#145  -  []  92.02 35.94 0 top
NOREF#146  -  []  79.7 83.31 0 top
NOREF#147  -  []  128.53 104.97 90 top
NOREF#148  -  []  128.53 104.97 90 top
NOREF#149  -  []  78.81 111.48 0 top
NOREF#150  -  []  4.52 38.21 0 top
NOREF#151  -  []  118.18 51.26 0 top
NOREF#152  -  []  0 129.49 0 top
NOREF#153  -  []  43.25 92.46 0 top
NOREF#154  -  []  117.23 2.06 90 top
NOREF#155  -  []  30.55 124.76 90 top
NOREF#156  -  []  19.22 64.65 0 top
NOREF#157  -  []  29.81 27.41 90 top
NOREF#158  -  []  121.74 8.25 0 top
NOREF#159  -  []  13.5 89.07 0 top
NOREF#160  -  []  31.19 50.27 0 top
NOREF#161  -  []  117.61 7.36 90 top
NOREF#162  -  []  96.82 58.75 0 top
NOREF#163  -  []  79.46 94.67 0 top
NOREF#164  -  []  71.75 90.53 0 top
NOREF#165  -  []  121.74 106.19 0 top
NOREF#166  -  []  67.01 59.9 0 top
NOREF#167  -  []  101.64 32.86 0 top
NOREF#168  -  []  126.07 105.07 90 top
NOREF#169  -  []  89.42 92.14 90 top
NOREF#170  -  []  24.71 57.51 90 top
NOREF#171  -  []  98.75 51.26 0 top
NOREF#172  -  []  118.06 59.37 90 top
NOREF#173  -  []  26.05 117.76 90 top
NOREF#174  -  []  123.43 71.61 90 top
NOREF#175  -  []  112.79 75.23 90 top
NOREF#176  -  []  3.16 45.9 0 top
NOREF#177  -  []  93.67 54.21 0 top
NOREF#178  -  []  117.06 3.36 0 top
NOREF#179  -  []  112.31 36.26 90 top
NOREF#180  -  []  19.82 74.66 90 top
NOREF#181  -  []  26.51 85.24 0 top
NOREF#182  -  []  46.97 35.03 90 top
NOREF#183  -  []  29.54 27.29 0 top
NOREF#184  -  []  87.72 113.01 90 top
NOREF#185  -  []  8.24 42.4 90 top
NOREF#186  -  []  111.98 38.05 90 top
NOREF#187  -  []  46.53 69.11 0 top
NOREF#188  -  []  45.29 119.21 0 top
NOREF#189  -  []  -0.15 30.35 0 top
NOREF#190  -  []  94.47 34.51 90 top
NOREF#191  -  []  120.85 71.61 0 top
NOREF#192  -  []  41.23 103.59 0 top
NOREF#193  -  []  21.55 124.76 0 top
NOREF#194  -  []  16.03 91.68 0 top
NOREF#195  -  []  20.79 65.57 90 top
NOREF#196  -  []  93.47 54.12 0 top
NOREF#197  -  []  41.01 70.95 90 top
NOREF#198  -  []  13.48 83.87 90 top
NOREF#199  -  []  -0.02 29.15 0 top
NOREF#200  -  []  21.68 98.15 90 top
NOREF#201  -  []  7.67 7.9 90 top
NOREF#202  -  []  4.3 51.38 90 top
NOREF#203  -  []  62.59 37.47 0 top
NOREF#204  -  []  43.26 116.14 0 top
NOREF#205  -  []  57.12 14.55 0 top
NOREF#206  -  []  18.22 74.66 0 top
NOREF#207  -  []  121.9 71.61 90 top
NOREF#208  -  []  91.9 35.67 90 top
NOREF#209  -  []  99.38 34.78 90 top
NOREF#210  -  []  91.9 34.52 90 top
NOREF#211  -  []  4.42 51.65 0 top
NOREF#212  -  []  -7.05 0 90 top
NOREF#213  -  []  117.23 4.66 0 top
NOREF#214  -  []  30.09 27.29 90 top
NOREF#215  -  []  76.01 103.95 90 top
NOREF#216  -  []  16.03 91.68 0 top
NOREF#217  -  []  122.38 73 90 top
NOREF#218  -  []  111.21 36.44 90 top
NOREF#219  -  []  32.78 37.97 0 top
NOREF#220  -  []  117.13 52.36 90 top
NOREF#221  -  []  0 129.49 0 top
NOREF#222  -  []  101.17 33.76 0 top
NOREF#223  -  []  107.39 53.79 90 top
NOREF#224  -  []  90.06 3.63 0 top
NOREF#225  -  []  110.03 37.83 0 top
NOREF#226  -  []  12.41 74.76 90 top
NOREF#227  -  []  122.38 73.55 0 top
NOREF#228  -  []  71.08 51.24 90 top
NOREF#229  -  []  13.03 85.74 0 top
NOREF#230  -  []  101.14 35.03 90 top
NOREF#231  -  []  94.67 53.32 90 top
NOREF#232  -  []  13.03 84.69 90 top
NOREF#233  -  []  26.73 80.24 0 top
NOREF#234  -  []  86.87 68.52 0 top
NOREF#235  -  []  46.03 0.59 90 top
NOREF#236  -  []  134.58 4.95 0 top
NOREF#237  -  []  118.27 9.51 0 top
NOREF#238  -  []  4.01 7 0 top
NOREF#239  -  []  117.74 7.64 0 top
NOREF#240  -  []  97.7 56.36 0 top
NOREF#241  -  []  62.95 59.37 0 top
NOREF#242  -  []  82.26 83.93 90 top
NOREF#243  -  []  108.64 52.1 90 top
NOREF#244  -  []  46.21 28.55 90 top
NOREF#245  -  []  26.51 83.64 90 top
NOREF#246  -  []  16.89 64.55 0 top
NOREF#247  -  []  63.59 37.47 90 top
NOREF#248  -  []  87.72 114.66 90 top
NOREF#249  -  []  96.67 74.6 90 top
NOREF#250  -  []  21.41 99.08 0 top
NOREF#251  -  []  24.84 57.78 0 top
NOREF#252  -  []  17.91 64.65 0 top
NOREF#253  -  []  89.9 91.57 0 top
NOREF#254  -  []  96.33 33.24 0 top
NOREF#255  -  []  81.68 97.96 90 top
NOREF#256  -  []  122.38 71.61 0 top
NOREF#257  -  []  101.24 74.47 90 top
NOREF#258  -  []  13.5 89.07 0 top
NOREF#259  -  []  62.66 37.65 0 top
NOREF#260  -  []  71.61 55.3 90 top
NOREF#261  -  []  109.95 75.76 90 top
NOREF#262  -  []  125.08 51.26 90 top
NOREF#263  -  []  4.52 38.21 90 top
NOREF#264  -  []  118.82 8.46 90 top
NOREF#265  -  []  46.05 35.31 0 top
NOREF#266  -  []  13.3 84.82 90 top
NOREF#267  -  []  87.45 113.94 0 top
NOREF#268  -  []  16.89 64.55 0 top
NOREF#269  -  []  43.38 116.97 0 top
NOREF#270  -  []  0 129.49 0 top
NOREF#271  -  []  101.54 32.71 0 top
NOREF#272  -  []  102.22 33.76 90 top
NOREF#273  -  []  46.07 116.18 90 top
NOREF#274  -  []  11.21 73.97 0 top
NOREF#275  -  []  15.15 93.47 0 top
NOREF#276  -  []  117.14 59.64 0 top
NOREF#277  -  []  39.65 19.35 0 top
NOREF#278  -  []  105.65 51.26 90 top
NOREF#279  -  []  130.67 111.59 90 top
NOREF#280  -  []  27.73 47.81 0 top
NOREF#281  -  []  42.33 103.46 0 top
NOREF#282  -  []  13.48 89.87 0 top
NOREF#283  -  []  16.99 65.57 90 top
NOREF#284  -  []  27.66 47.63 0 top
NOREF#285  -  []  91.9 35.67 0 top
NOREF#286  -  []  128.53 107.07 90 top
NOREF#287  -  []  98.66 34.5 90 top
NOREF#288  -  []  126.01 7 0 top
NOREF#289  -  []  45.92 35.03 0 top
NOREF#290  -  []  99.23 34.68 0 top
NOREF#291  -  []  -7.05 -0.05 0 top
NOREF#292  -  []  13.5 84.67 90 top
NOREF#293  -  []  2.65 83.76 0 top
NOREF#294  -  []  48.2 94.9 0 top
NOREF#295  -  []  7.84 45.07 90 top
NOREF#296  -  []  12.81 73.97 90 top
NOREF#297  -  []  3.46 48.6 0 top
NOREF#298  -  []  42.37 15.08 90 top
NOREF#299  -  []  97.96 67.79 0 top
NOREF#300  -  []  129.49 0 90 top
NOREF#301  -  []  42.33 95.71 90 top
NOREF#302  -  []  95.37 34.17 90 top
NOREF#303  -  []  96.49 34.16 90 top
NOREF#304  -  []  131.28 104.34 0 top
NOREF#305  -  []  88 114.54 90 top
NOREF#306  -  []  78.81 111.48 90 top
NOREF#307  -  []  96.69 59.03 0 top
NOREF#308  -  []  117.61 7.91 0 top
NOREF#309  -  []  50.11 6.96 90 top
NOREF#310  -  []  2.54 77.78 0 top
NOREF#311  -  []  14.28 89.84 0 top
NOREF#312  -  []  118.53 5.88 90 top
NOREF#313  -  []  108.35 75.23 90 top
NOREF#314  -  []  41.23 95.59 90 top
NOREF#315  -  []  16.28 89.84 0 top
NOREF#316  -  []  26.05 117.76 90 top
NOREF#317  -  []  77.43 104.07 90 top
NOREF#318  -  []  111.98 38.05 0 top
NOREF#319  -  []  7.67 7.9 0 top
NOREF#320  -  []  4 4 90 top
NOREF#321  -  []  88 112.89 90 top
NOREF#322  -  []  25.71 84.84 0 top
NOREF#323  -  []  45.16 29.1 0 top
NOREF#324  -  []  0 129.49 0 top
NOREF#325  -  []  26.05 117.76 90 top
NOREF#326  -  []  6.54 68.78 90 top
NOREF#327  -  []  108.35 75.23 0 top
NOREF#328  -  []  121.87 105.92 0 top
NOREF#329  -  []  81.95 100.59 90 top
NOREF#330  -  []  -151.42 75.84 0 top
NOREF#331  -  []  50.88 13.95 90 top
NOREF#332  -  []  6.72 25.15 90 top
NOREF#333  -  []  60.25 15.27 90 top
NOREF#334  -  []  32.08 58.14 0 top
NOREF#335  -  []  98.26 75.13 90 top
NOREF#336  -  []  49.99 13.75 0 top
NOREF#337  -  []  89.42 92.14 0 top
NOREF#338  -  []  63.52 37.65 90 top
NOREF#339  -  []  121.74 105.64 90 top
NOREF#340  -  []  33.13 58.14 90 top
NOREF#341  -  []  110.16 38.11 0 top
NOREF#342  -  []  -176.99 -147.62 0 top
NOREF#343  -  []  15.1 92.85 90 top
NOREF#344  -  []  13.5 89.07 90 top
NOREF#345  -  []  79.46 94.67 90 top
NOREF#346  -  []  3.16 45.9 90 top
NOREF#347  -  []  50.24 7.24 0 top
NOREF#348  -  []  13.82 95.32 0 top
NOREF#349  -  []  116.66 104.7 0 top
NOREF#350  -  []  0 129.49 0 top
NOREF#351  -  []  85.77 76.48 0 top
NOREF#352  -  []  117.01 59.36 0 top
NOREF#353  -  []  4.01 129 0 top
NOREF#354  -  []  26.73 80.64 0 top
NOREF#355  -  []  121.62 8.53 0 top
NOREF#356  -  []  89.9 91.57 90 top
NOREF#357  -  []  7.97 42.53 90 top
NOREF#358  -  []  44.7 67.27 90 top
NOREF#359  -  []  0 129.49 0 top
NOREF#360  -  []  13.5 86.67 90 top
NOREF#361  -  []  16.86 91.8 90 top
NOREF#362  -  []  41.1 41.38 0 top
NOREF#363  -  []  4.3 51.38 0 top
NOREF#364  -  []  7.57 44.94 0 top
NOREF#365  -  []  112.79 75.23 0 top
NOREF#366  -  []  48.3 95.18 0 top
NOREF#367  -  []  134.58 120.05 0 top
NOREF#368  -  []  121.95 46.59 90 top
NOREF#369  -  []  26.05 123.76 90 top
NOREF#370  -  []  125.85 106.97 90 top
NOREF#371  -  []  97.61 34.5 0 top
NOREF#372  -  []  55.25 15.27 0 top
NOREF#373  -  []  31.05 116.76 90 top
NOREF#374  -  []  114.39 75.76 90 top
NOREF#375  -  []  16.99 65.57 0 top
NOREF#376  -  []  43.13 92.18 0 top
NOREF#377  -  []  96.49 34.16 0 top
NOREF#378  -  []  41.22 41.66 0 top
NOREF#379  -  []  120.98 71.88 0 top
NOREF#380  -  []  5.36 46.4 90 top
NOREF#381  -  []  42.15 41.38 90 top
NOREF#382  -  []  96.67 74.6 0 top
NOREF#383  -  []  44.18 92.18 90 top
NOREF#384  -  []  21.96 97.48 90 top
NOREF#385  -  []  4 126 0 top
NOREF#386  -  []  96.76 34.28 90 top
NOREF#387  -  []  128.53 104.97 90 top
NOREF#388  -  []  -1.06 96.91 90 bottom
NOREF#389  -  []  34.94 76.63 270 bottom
NOREF#390  -  []  105.05 16.15 180 bottom
NOREF#391  -  []  42.21 76.63 270 bottom
NOREF#392  -  []  89.68 46.13 180 bottom
NOREF#393  -  []  44.25 114.22 180 bottom
NOREF#394  -  []  131.03 26.17 270 bottom
NOREF#395  -  []  89.55 38.68 180 bottom
NOREF#396  -  []  131.02 100.93 270 bottom
NOREF#397  -  []  14.44 103.71 270 bottom
NOREF#398  -  []  -1.02 31.94 90 bottom
P4  ESD8472MUT5G  [DIO-0201]  50.77 6.1 0 top
P5  ESD8472MUT5G  [DIO-0201]  55.59 6.22 180 top
P6  ESD8472MUT5G  [DIO-0201]  52.67 6.22 0 top
P7  ESD8472MUT5G  [DIO-0201]  53.94 6.22 180 top
P8  ESD8472MUT5G  [DIO-0201]  47.08 16.76 270 top
P10  ESD8472MUT5G  [DIO-0201]  42.13 8 0 bottom
P11  ESD8472MUT5G  [DIO-0201]  47.08 15.49 90 top
P12  ESD8472MUT5G  [DIO-0201]  31.97 98.17 0 top
P13  ESD8472MUT5G  [DIO-0201]  74.26 14.48 0 top
P14  ESD8472MUT5G  [DIO-0201]  75.66 14.48 180 top
P17  ESD8472MUT5G  [DIO-0201]  123.92 105.79 90 top
P18  ESD8472MUT5G  [DIO-0201]  123.92 108.58 270 top
P19  ESD8472MUT5G  [DIO-0201]  123.92 107.31 90 top
P20  ESD8472MUT5G  [DIO-0201]  110.3 61.18 90 bottom
P21  ESD8472MUT5G  [DIO-0201]  110.3 62.83 90 bottom
P22  ESD8472MUT5G  [DIO-0201]  110.55 43.78 90 bottom
P23  ESD8472MUT5G  [DIO-0201]  110.55 46.2 90 bottom
P24  ESD8472MUT5G  [DIO-0201]  110.3 59.4 270 bottom
P25  ESD8472MUT5G  [DIO-0201]  110.55 48.74 90 bottom
P26  ESD8472MUT5G  [DIO-0201]  110.3 64.23 90 bottom
P27  ESD8472MUT5G  [DIO-0201]  110.3 65.88 270 bottom
Q2  SSM6J501NU  [UDFN-6L_0P65_2X2_EP]  29.01 106.91 0 top
Q5  2N7002L  [SOT23_123]  40.48 97.28 180 top
Q6  NTK3139PT1G  [SOT723-3L_0P4_1P2X0P8]  94.07 53.72 0 bottom
Q7  2N7002L  [SOT23_123]  95.34 59.05 180 bottom
Q8  MMBT3904  [SOT23_123]  104.96 50.13 270 bottom
Q17  MMBT2907A  [SOT23-3L_1P9_3P12X1P5]  41.75 108.2 180 top
Q24  NTK3139PT1G  [SOT723-3L_0P4_1P2X0P8]  50.39 14.35 270 bottom
Q25  2N7002L  [SOT23_123]  53.18 16.13 270 bottom
Q32  SSM6J501NU  [UDFN-6L_0P65_2X2_EP]  9.36 117.73 90 top
Q34  SSM6J501NU  [UDFN-6L_0P65_2X2_EP]  11.65 107.19 270 top
Q35  BC857BS  [SOT363_6]  8.48 104.27 90 top
Q37  2N7002L  [SOT23_123]  23.97 91.06 180 top
Q38  CSD25481F4  [MOSFET_0402-3L_A1]  23.21 42.42 270 bottom
Q39  2N7002L  [SOT23_123]  11.78 52.58 180 bottom
Q40  MMBT3904  [SOT23_123]  3.52 91.44 90 top
Q41  MMBT3904  [SOT23_123]  12.76 79.32 90 bottom
R1  1K  [R0402]  32.22 96.9 180 top
R4  1K  [R0402]  36.03 98.42 270 top
R6  100K  [R0402]  40.99 101.09 90 top
R8  100K  [R0402]  40.48 99.57 0 top
R12  4.7K  [R0402]  43.53 122.43 270 top
R30  0E  [R0402]  80.07 82.14 0 bottom
R31  100K  [R0402]  18.51 91.82 0 bottom
R32  0E  [R0402]  75.88 81.89 135 bottom
R33  2.2K  [R0402]  50.19 76.68 225 bottom
R34  2.2K  [R0402]  49.41 77.44 225 bottom
R35  100K  [R0402]  68.34 80.98 315 bottom
R36  4.75M  [R0402]  77.1 90.05 225 top
R37  31.6K  [R0402]  14.06 91.57 0 top
R38  1M  [R0402]  72.89 81.68 225 top
R39  22E  [R0402]  61.82 67.31 135 top
R40  29.4K  [0402]  16.86 92.2 270 bottom
R41  22E  [R0402]  61.11 66.6 135 top
R42  22E  [R0402]  55.55 71.35 45 bottom
R43  22E  [R0402]  62.45 67.94 135 top
R44  22E  [R0402]  56.29 70.62 45 bottom
R45  0E  [R0402]  79 72.08 315 top
R46  0E  [R0402]  78.25 71.35 315 top
R47  0E  [R0402]  18.13 80.9 270 top
R49  22E  [R0402]  58.39 72.14 135 top
R61  2.2K  [R0402]  66.41 75.46 225 bottom
R62  2.2K  [R0402]  65.65 76.21 225 bottom
R63  2.2K  [R0402]  65.03 74.09 315 bottom
R64  2.2K  [R0402]  63.27 72.98 270 bottom
R65  0E  [R0402]  56.12 74.92 315 bottom
R66  200E  [R0402]  54.72 72.15 45 bottom
R67  470K  [R0402]  56.84 75.65 135 bottom
R68  10K  [R0402]  51.82 74.91 225 top
R69  0E  [R0402]  54 76.55 225 bottom
R70  200E  [R0402]  52.53 74.19 45 top
R71  470K  [R0402]  54.93 77.77 315 bottom
R75  100K  [R0402]  77.14 87.19 135 top
R76  0E  [R0402]  75.61 88.71 315 top
R80  4.7K  [R0402]  67.94 92.4 225 bottom
R81  240E  [R0402]  65.5 111.53 90 bottom
R82  240E  [R0402]  47.71 111.52 0 bottom
R83  240E  [R0402]  69.33 113.87 270 bottom
R84  240E  [R0402]  47.71 110.44 0 bottom
R85  0E  [R0402]  54.12 95.91 135 bottom
R86  240E  [R0402]  65.85 93.99 315 bottom
R90  470E  [R0402]  69.96 109.76 45 bottom
R91  470E  [R0402]  52.06 110.28 45 bottom
R92  10K  [R0402]  46.19 92.58 90 bottom
R93  10K  [R0402]  67.86 68.71 315 top
R94  10K  [R0402]  66.79 67.67 135 top
R95  49.9E  [R0402]  74.52 74.04 135 top
R96  0E  [R0402]  105.5 72.01 90 bottom
R97  0E  [R0402]  104.36 72.01 90 bottom
R99  10K  [R0402]  109.53 48.99 270 bottom
R100  10K  [R0402]  108.64 65.63 0 bottom
R101  10K  [R0402]  108.64 64.36 0 bottom
R102  0E  [R0402]  95.72 53.72 270 bottom
R103  60.4E  [R0805]  98.26 59.31 90 bottom
R104  10K  [R0402]  95.85 56.64 0 bottom
R105  10K  [R0402]  94.07 55.12 180 bottom
R106  33E  [R0402]  110.3 57.75 270 bottom
R107  2.2K  [R0402]  92.42 53.72 270 bottom
R108  10K  [R0402]  107.25 48.99 90 bottom
R109  10E  [R0402]  11.52 32.89 0 bottom
R110  33E  [R0402]  51.85 74.96 225 bottom
R116  10K  [R0402]  61.18 100.2 270 bottom
R117  10K  [R0402]  61.15 104.97 0 bottom
R118  10K  [R0402]  63.21 106.93 0 top
R124  33E  [R0402]  68.8 66.93 270 bottom
R125  33E  [R0402]  64.36 62.36 225 top
R126  100K  [R0402]  55.85 22.86 270 bottom
R127  4.7K  [R0402]  89.76 90.68 0 top
R129  2.2K  [R0402]  40.61 34.8 270 bottom
R130  0E  [R0402]  40.35 32 0 top
R131  10K  [R0402]  29.56 33.53 0 bottom
R145  470E  [R0402]  122.69 87 180 bottom
R146  470E  [R0402]  122.69 88.14 180 bottom
R147  470E  [R0402]  122.69 89.28 180 bottom
R155  10K  [R0402]  75.28 99.44 135 top
R157  470E  [R0402]  98.01 114.94 0 bottom
R158  22E  [R0402]  121.94 108.47 0 top
R159  1.5K  [R0402]  105.9 119.78 90 bottom
R160  22E  [R0402]  121.94 107.38 0 top
R161  1K  [R0402]  126.2 121.67 180 bottom
R162  1K  [R0402]  126.2 119.25 180 bottom
R163  0E  [R0402]  123.85 111.81 180 top
R164  1M  [R0402]  98.08 113.3 90 bottom
R165  10K  [R0402]  100.17 119.51 90 bottom
R166  1K  [R0402]  126.2 116.71 180 bottom
R167  1K  [R0402]  126.2 114.43 180 bottom
R168  10K  [R0402]  113.63 103.12 270 bottom
R169  10K  [R0402]  111.35 103.12 270 bottom
R170  10K  [R0402]  109.06 103 270 bottom
R171  0E  [R0402]  107.15 101.73 90 bottom
R172  0E  [R0402]  112.49 103.12 90 bottom
R174  4.7K  [R0402]  71.76 80.16 135 top
R176  0E  [R0402]  102.33 18.16 0 top
R177  0E  [R0402]  102.33 19.43 0 top
R178  0E  [R0402]  102.33 17.02 0 top
R179  0E  [R0402]  102.33 15.88 0 top
R180  0E  [R0402]  102.33 14.73 0 top
R181  0E  [R0402]  102.33 13.59 0 top
R182  2.2K  [R0402]  91.79 46.61 270 top
R203  4.7K  [R0402]  2.63 12.57 0 top
R204  4.7K  [R0402]  2.63 9.91 0 top
R206  4.7K  [R0402]  2.63 14.99 0 top
R209  4.7K  [R0402]  2.76 20.07 0 top
R210  4.7K  [R0402]  2.76 17.53 0 top
R211  4.7K  [R0402]  2.76 22.61 0 top
R212  4.7K  [R0402]  2.76 27.69 0 top
R213  4.7K  [R0402]  2.76 25.15 0 top
R224  10K  [R0402]  77.18 22.35 90 top
R231  2.2K  [R0402]  69.56 69.72 225 top
R232  0E  [R0402]  22.85 85.71 270 bottom
R233  0E  [R0402]  86.58 61.59 180 top
R234  0E  [R0402]  88.61 125.73 180 top
R235  2.2K  [R0402]  72.1 72.39 45 top
R236  0E  [R0402]  23.99 85.71 270 bottom
R237  0E  [R0402]  86.58 62.87 180 top
R238  0E  [R0402]  88.61 123.19 0 top
R242  0E  [R0402]  118.58 48.39 180 top
R245  60.4E  [R0805]  75.53 18.8 90 top
R246  60.4E  [R0805]  73.63 18.8 90 top
R247  0E  [R0402]  118.58 45.72 180 top
R249  47K  [R0402]  95.09 68.33 90 top
R250  0E  [R0402]  46.45 25.27 90 bottom
R251  0E  [R0402]  47.51 3.81 90 top
R252  10K  [R0402]  59.74 22.89 90 bottom
R253  10K  [R0402]  54.7 22.86 90 bottom
R254  100K  [R0402]  60.8 22.86 270 bottom
R255  10K  [R0402]  58.47 22.89 90 bottom
R257  10K  [R0402]  54.07 18.8 90 bottom
R269  0E  [R0402]  8.09 40.89 270 top
R278  49.9E  [R0402]  33.88 40.64 90 top
R279  49.9E  [R0402]  32.73 40.64 90 top
R280  49.9E  [R0402]  31.59 40.64 90 top
R281  49.9E  [R0402]  30.45 40.64 90 top
R282  49.9E  [R0402]  35.02 40.64 90 top
R283  49.9E  [R0402]  29.3 40.64 90 top
R284  0E  [R0402]  74.31 80.93 315 top
R285  0E  [R0402]  77.91 88.56 315 top
R286  22E  [R0402]  59.86 71.04 45 bottom
R287  22E  [R0402]  58.24 72.62 45 bottom
R288  22E  [R0402]  57.07 69.87 45 bottom
R289  22E  [R0402]  58.95 71.92 45 bottom
R290  22E  [R0402]  60.64 70.27 45 bottom
R291  22E  [R0402]  57.42 73.45 45 bottom
R293  470E  [R0402]  20.92 33.66 90 top
R294  10K  [R0402]  111.75 115.12 180 bottom
R295  1K  [R0402]  3.65 35.69 180 top
R296  1K  [R0402]  3.65 33.15 180 top
R297  470E  [R0402]  18 7.37 90 top
R300  2.49K  [R0402]  28.16 40.64 270 top
R301  10K  [R0402]  24.6 30.73 270 top
R302  10K  [R0402]  22.32 30.73 270 top
R303  470E  [R0402]  38.32 7.37 90 bottom
R306  5.76K  [R0402]  27.02 40.64 90 top
R307  2.49K  [R0402]  25.75 30.73 90 top
R308  2.49K  [R0402]  23.46 30.73 90 top
R309  1K  [R0402]  97.09 60.4 0 top
R310  1K  [R0402]  115.5 59.64 0 top
R325  0E  [R0402]  79.83 72.88 315 top
R347  1K  [R0402]  87.47 80.52 270 top
R348  100K  [R0402]  93.44 93.47 90 top
R349  1M  [R0402]  100.8 85.47 0 top
R350  0E  [R0402]  89.76 95.38 180 top
R356  33E  [R0402]  12.45 37.89 0 bottom
R357  33E  [R0402]  12.45 38.86 0 bottom
R358  33E  [R0402]  12.45 39.8 0 bottom
R366  33K  [R0402]  111.98 33.53 90 top
R367  10K  [R0402]  114.52 38.99 270 top
R380  0E  [0402]  48.48 94.61 135 top
R381  0E  [0402]  43.65 92.46 0 top
R387  10K  [R0402]  72.85 78.25 315 top
R436  22E  [R0402]  63.83 69.27 135 top
R437  22E  [R0402]  63.18 68.62 135 top
R438  22E  [R0402]  68.32 73.77 135 top
R439  22E  [R0402]  68.95 74.39 135 top
R440  22E  [R0402]  67.66 73.11 135 top
R441  22E  [R0402]  66.37 71.8 135 top
R442  22E  [R0402]  64.47 69.91 135 top
R443  22E  [R0402]  65.73 71.17 135 top
R444  22E  [R0402]  65.11 70.54 135 top
R445  22E  [R0402]  67 72.45 135 top
R446  22E  [R0402]  69.58 75.03 135 top
R447  22E  [R0402]  70.22 75.66 135 top
R448  10K  [R0402]  21.81 90.55 90 top
R449  10K  [R0402]  80.99 92.96 315 top
R483  0E  [R0402]  91.28 36.07 0 top
R485  0E  [R0402]  48.6 78.22 225 bottom
R486  0E  [R0402]  91.28 38.35 0 top
R487  0E  [R0402]  91.28 37.21 0 top
R491  2.2K  [R0402]  108.39 48.99 90 bottom
R504  0E  [R0402]  101.44 86.78 90 bottom
R506  0E  [R0402]  102.58 86.78 90 bottom
R508  0E  [R0402]  12.45 40.96 0 bottom
R509  0E  [R0402]  12.45 41.88 0 bottom
R515  0E  [0402]  92.42 35.94 180 bottom
R516  0E  [0402]  25.24 57.78 180 top
R520  0E  [0402]  92.42 34.8 180 bottom
R521  0E  [0402]  32.61 58.42 0 top
R525  49.9E  [R0402]  48.1 82.56 45 bottom
R526  49.9E  [R0402]  48.85 81.84 45 bottom
R527  49.9E  [R0402]  50.35 80.37 45 bottom
R528  49.9E  [R0402]  47.19 83.4 45 bottom
R530  49.9E  [R0402]  49.6 81.11 45 bottom
R532  49.9E  [R0402]  51.27 79.49 45 bottom
R537  10K  [R0402]  46.07 114.05 90 top
R538  300E  [0402]  43.78 116.97 180 top
R539  100K  [R0402]  33.75 104.9 90 top
R558  0E  [R0402]  54.21 75.85 225 top
R559  0E  [R0402]  55.23 74.94 225 top
R565  0E  [R0402]  53.24 72.03 315 top
R566  0E  [R0402]  54.14 72.92 315 top
R567  0E  [R0402]  112.9 98.96 270 bottom
R568  0E  [R0402]  114.01 98.96 270 bottom
R569  0E  [R0402]  61.69 16.13 270 bottom
R570  100K  [R0402]  50.39 16 180 bottom
R571  0E  [R0402]  50.39 12.83 0 bottom
R590  33E  [R0402]  19.52 41.02 270 bottom
R591  33E  [R0402]  18.28 41.02 270 bottom
R592  33E  [R0402]  17.11 41.02 270 bottom
R593  33E  [R0402]  15.99 41.02 270 bottom
R595  0E  [0402]  77.43 104.47 90 bottom
R596  0E  [0402]  76.29 104.47 90 bottom
R597  33E  [R0402]  75.17 96.07 225 top
R598  33E  [R0402]  75.95 95.3 225 top
R604  10K  [R0402]  83.24 95.19 315 top
R605  140E  [R0402]  72.5 94.07 315 top
R606  75E  [R0402]  71.68 93.26 135 top
R607  140E  [R0402]  73.9 92.65 135 top
R608  75E  [R0402]  73.11 91.87 315 top
R613  10K  [R0402]  15.21 119 90 top
R614  100K  [R0402]  14.06 119 270 top
R615  10K  [R0402]  8.09 102.23 0 top
R616  47K  [R0402]  9.24 106.17 0 top
R617  0E  [R0402]  60.28 102.75 90 top
R618  0E  [R0402]  59.27 102.75 90 top
R622  10K  [R0402]  2.93 40.43 0 top
R623  1K  [R0402]  4.92 50.42 0 bottom
R630  10K  [R0402]  9.31 48.95 90 top
R632  0E  [R0402]  76.74 94.16 225 top
R633  0E  [R0402]  77.56 93.44 225 top
R634  49.9E  [R0402]  113.94 72.62 180 bottom
R635  49.9E  [R0402]  111.91 72.62 0 bottom
R636  10K  [R0402]  12.18 50.32 0 bottom
R637  10K  [R0402]  12.29 54.86 0 bottom
R638  4.7K  [R0402]  32.65 55.01 180 top
R639  4.7K  [R0402]  25.2 55.33 0 top
R640  10K  [R0402]  32.65 56.19 0 top
R641  0E  [R0402]  76.87 82.09 0 top
R644  0E  [R0402]  112.38 71.05 90 bottom
R645  0E  [R0402]  113.48 71.06 90 bottom
R656  10K  [R0402]  7.21 59.05 90 top
R658  10K  [R0402]  118.58 47.24 0 top
R660  0E  [R0402]  92.47 42.29 90 top
R663  5.76K  [R0402]  26.89 30.73 270 top
R664  5.76K  [R0402]  25.87 38.61 180 top
